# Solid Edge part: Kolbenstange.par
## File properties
Last saved by: ahadarics
Revision: 77
Dokumentum tartalom típus: 0
Sűrűség: 0,000 kg/m^3
Pontosság: 0,990
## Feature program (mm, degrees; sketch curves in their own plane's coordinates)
base feature "unnamed BaseFeature 1"
sketch for "Furat_1" plane through (0, 0, 14.5) normal (0, 0, 1) x-axis (0, -1, 0)
  hole centre (0, 0) bore radius 3.3235
hole "Furat_1" nominal diameter 8 finite  ThreadDepth = 15 mm
sketch for "Kihúzás_1" plane through (0, 0, -28) normal (0, 0, -1) x-axis (0, 1, 0)
  circle centre (0, 0) radius 20
extrude "Kihúzás_1" add finite 16 along -normal
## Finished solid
Body 1: solid body, 15 faces, 21 edges, 8 vertices.
  Faces by surface: plane 8, cylinder 4, cone 2, torus 1
  Edges by curve: circle 11, line 6, ellipse 2, intersection 2
Bounding box of the edges (mm; curved faces can reach further): 40.000 x 40.000 x 42.514, from (-20, -20, -28) to (20, 20, 14.5137).
Cylindrical faces by radius (mm): R3.32 x1, R3.3235 x1, R6 x1, R20 x1
Conical faces (half-angle, radius in mm at the cone's reference point): 45 deg R3.32 x1, 59 deg R1.6618 x1
Toroidal faces (ring radius, tube radius in mm): R4.8 r1.2 x1
Planar faces by outward normal: +x 1, +z 3, -x 1, -z 1, oblique 2
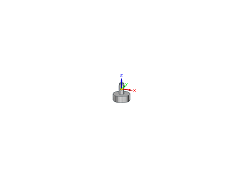
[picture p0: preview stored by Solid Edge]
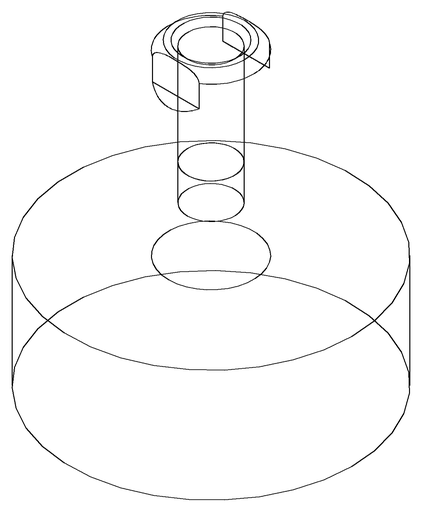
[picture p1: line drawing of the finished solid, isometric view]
